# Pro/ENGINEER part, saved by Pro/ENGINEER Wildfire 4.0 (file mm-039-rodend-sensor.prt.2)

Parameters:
  METRIC = "NO"

Other parameters: PITCH, DRILL_POINT_ANGLE, DRILL_DEPTH, DRILL_DIAMETER, THREAD_DIAMETER, THREADS_PER_INCH, THREAD_DEPTH, THREAD_LENGTH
